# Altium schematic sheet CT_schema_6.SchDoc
size 218 x 273 mm
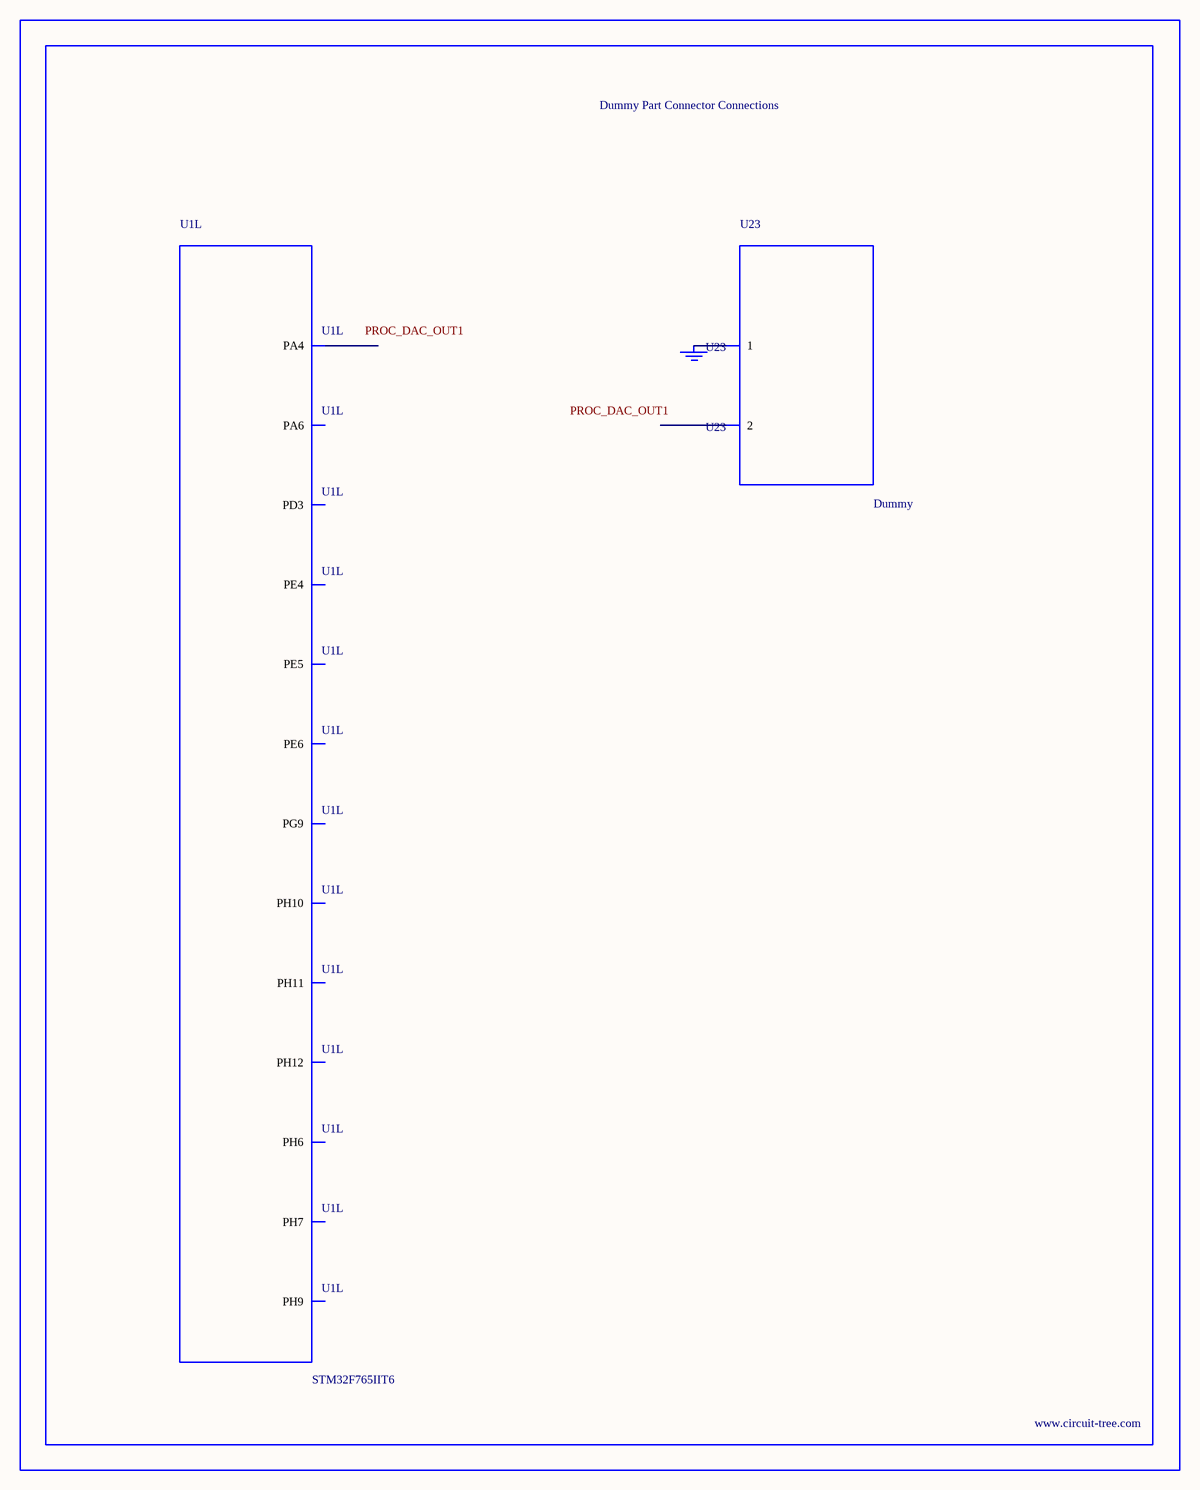
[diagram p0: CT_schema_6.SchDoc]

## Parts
BORDER5  (no value)
GND_INSTANCE_5_0  (no value)
U1  STM32F765IIT6  [LQFP176]  (part L of 12)
U23  Dummy  [DUMMY_PACKAGE_251]

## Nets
NetGND_INSTANCE_5_0_0: GND_INSTANCE_5_0.0(GND) U23.1

Not connected (* = marked no-connect by the designer): U1 3(PE4) 4(PE5) 5(PE6) 50(PA4) 52(PA6) 83(PH6) 84(PH7) 86(PH9) 87(PH10) 88(PH11) 89(PH12) 145(PD3) 152(PG9); U23 2

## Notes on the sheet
- Labels drawn without touching a wire or pin: PROC_DAC_OUT1

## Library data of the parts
BORDER5 = BORDER_PAGE5
GND_INSTANCE_5_0 = GND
